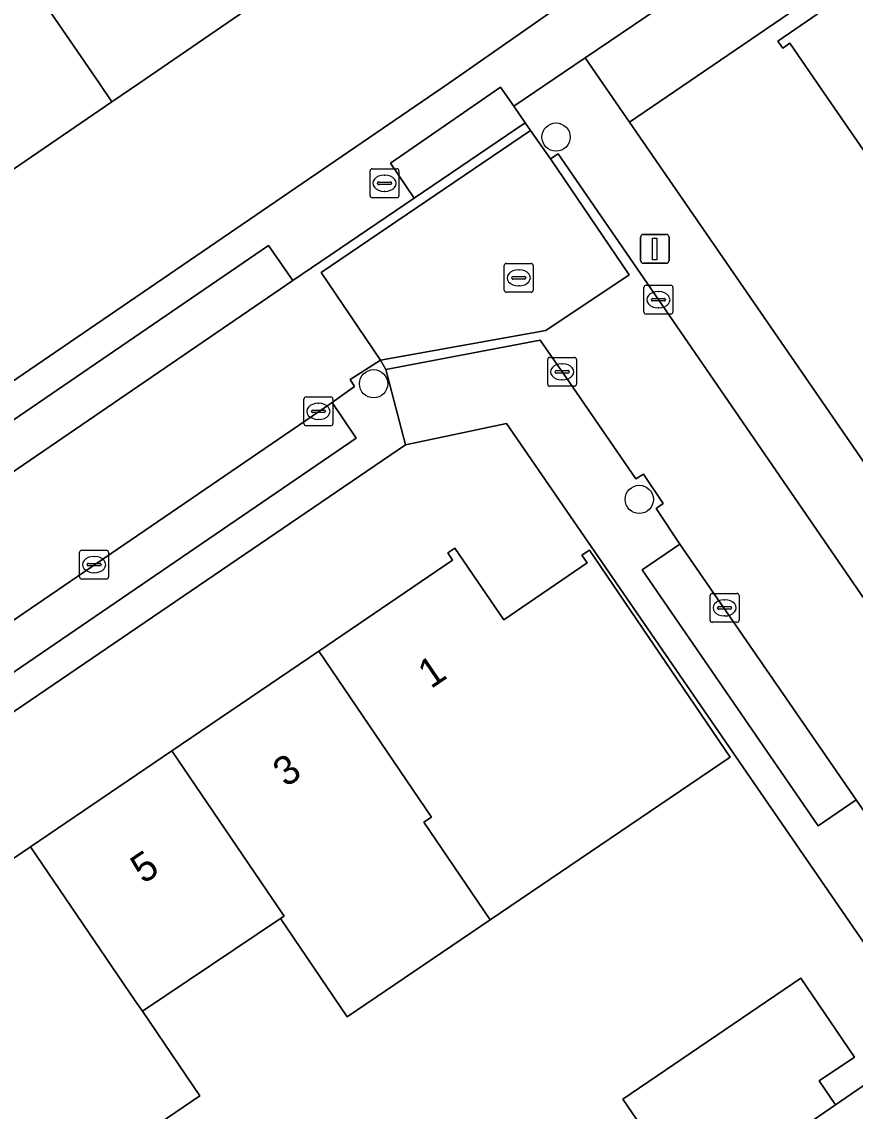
# Model space of a CAD drawing. Extents: x 157445 to 158888, y 383061 to 384688.
# Drawn here: x 158148.42 to 158177.28, y 383464.42 to 383502.14 of the extents above; entities that cross this region are included whole.
import ezdxf

# ---------------------------------------------------------------- set-up
doc = ezdxf.new("R2010")
doc.units = 0
for name, color, linetype in [('IMGEO_Boom', 7, 'Continuous'), ('IMGEO_Brandkraan', 7, 'Continuous'), ('IMGEO_Erf', 7, 'Continuous'), ('IMGEO_Kolk', 7, 'Continuous'), ('IMGEO_Lichtmast', 7, 'Continuous'), ('IMGEO_Pand', 7, 'Continuous'), ('IMGEO_Pand_nummerreeks', 7, 'Continuous'), ('IMGEO_Parkeervlak_open', 7, 'Continuous'), ('IMGEO_Rijbaan_lokaal_open', 7, 'Continuous'), ('IMGEO_Rioolput', 7, 'Continuous'), ('IMGEO_Voetpad_open', 7, 'Continuous')]:
    doc.layers.add(name, color=color, linetype=linetype)

msp = doc.modelspace()

# ---------------------------------------------------------------- linework, layer by layer
at = {"layer": 'IMGEO_Boom'}
for centre in [(158166.918, 383498.147), (158160.602, 383489.605), (158169.801, 383485.602)]:
    msp.add_circle(centre, 0.489, dxfattribs=at)
at = {"layer": 'IMGEO_Brandkraan'}
for p, q in [((158160.48, 383496.122), (158160.48, 383496.974)), ((158160.555, 383497.048), (158161.407, 383497.048)), ((158160.968, 383496.828), (158160.993, 383496.828)), ((158161.481, 383496.974), (158161.481, 383496.122)), ((158160.739, 383496.542), (158160.739, 383496.554)), ((158161.177, 383496.505), (158160.779, 383496.505)), ((158160.782, 383496.591), (158161.18, 383496.591)), ((158161.223, 383496.554), (158161.223, 383496.542)), ((158161.407, 383496.048), (158160.555, 383496.048)), ((158160.991, 383496.268), (158160.966, 383496.268))]:
    msp.add_line(p, q, dxfattribs=at)
for points in [[(158160.48, 383496.122), (158160.48, 383496.974)], [(158160.555, 383497.048), (158161.407, 383497.048)], [(158161.481, 383496.974), (158161.481, 383496.122)], [(158161.407, 383496.048), (158160.555, 383496.048)]]:
    msp.add_lwpolyline(points, dxfattribs=at)
for centre, radius, start, end in [((158160.557, 383496.972), 0.0765, 91.552, 178.448), ((158160.557, 383496.972), 0.0765, 91.552, 178.448), ((158161.405, 383496.972), 0.0765, 1.552, 88.448), ((158161.405, 383496.972), 0.0765, 1.552, 88.448), ((158160.779, 383496.551), 0.0403, 85.8775, 175.7526), ((158160.776, 383496.541), 0.0366, 178.938, 274.7102), ((158161.18, 383496.548), 0.043, 264.8664, 352.4533), ((158161.184, 383496.553), 0.0386, 1.7309, 96.639), ((158160.557, 383496.124), 0.0765, 181.552, 268.448), ((158160.557, 383496.124), 0.0765, 181.552, 268.448), ((158161.405, 383496.124), 0.0765, 271.552, 358.448), ((158161.405, 383496.124), 0.0765, 271.552, 358.448)]:
    msp.add_arc(centre, radius, start, end, dxfattribs=at)
for centre, major_axis, ratio, start_param, end_param in [((158160.967, 383496.548), (-0.387, 0.002), 0.722429, 4.712389, 7.853982), ((158160.992, 383496.548), (-0.39, 0.002), 0.717154, 1.570796, 4.712389)]:
    msp.add_ellipse(centre, major_axis=major_axis, ratio=ratio, start_param=start_param, end_param=end_param, dxfattribs=at)
at = {"layer": 'IMGEO_Erf'}
for points in [[(158099.535, 383456.505), (158112.557, 383465.403), (158163.191, 383500), (158166.785, 383502.503), (158174.8, 383507.947), (158171.578, 383512.706), (158171.33, 383512.536), (158171.16, 383512.783), (158166.413, 383509.536), (158161.426, 383506.125), (158156.37, 383502.667), (158152.47, 383500), (158151.545, 383499.368), (158146.628, 383496.004), (158141.637, 383492.59), (158136.791, 383489.276), (158131.721, 383485.809), (158126.874, 383482.494), (158121.76, 383478.996), (158116.93, 383475.693), (158111.816, 383472.194), (158107.026, 383468.918), (158101.876, 383465.396), (158097.013, 383462.07)], [(158186.515, 383510.296), (158169.458, 383498.667), (158173.045, 383493.459), (158193.833, 383463.284)], [(158178.381, 383496.502), (158175.975, 383500), (158175.016, 383501.394), (158174.769, 383501.224), (158174.599, 383501.472), (158180.671, 383505.651)], [(158170.025, 383463.669), (158169.233, 383464.836), (158175.397, 383469.02), (158177.25, 383466.289), (158176.027, 383465.464), (158176.593, 383464.64), (158179.881, 383466.9), (158165.205, 383488.229), (158161.709, 383487.492), (158141.032, 383473.406)], [(158143.63, 383470.113), (158148.729, 383473.576), (158153.616, 383476.896), (158158.702, 383480.35), (158163.339, 383483.5), (158163.171, 383483.749), (158163.42, 383483.918), (158165.106, 383481.436), (158168.002, 383483.402), (158167.816, 383483.675), (158168.073, 383483.849), (158172.942, 383476.675), (158164.643, 383471.043), (158159.691, 383467.682), (158157.378, 383471.09), (158152.597, 383467.878), (158154.587, 383464.947), (158149.242, 383461.318)]]:
    msp.add_lwpolyline(points, dxfattribs=at)
at = {"layer": 'IMGEO_Kolk'}
for p, q in [((158170.038, 383493.016), (158170.89, 383493.016)), ((158169.963, 383492.09), (158169.963, 383492.942)), ((158170.451, 383492.796), (158170.476, 383492.796)), ((158170.964, 383492.942), (158170.964, 383492.09)), ((158170.222, 383492.51), (158170.222, 383492.522)), ((158170.66, 383492.473), (158170.262, 383492.473)), ((158170.265, 383492.559), (158170.663, 383492.559)), ((158170.474, 383492.236), (158170.449, 383492.236)), ((158170.706, 383492.522), (158170.706, 383492.51)), ((158170.89, 383492.016), (158170.038, 383492.016)), ((158166.629, 383489.593), (158166.629, 383490.445)), ((158166.704, 383490.519), (158167.556, 383490.519)), ((158167.63, 383490.445), (158167.63, 383489.593)), ((158166.888, 383490.013), (158166.888, 383490.025)), ((158167.326, 383489.976), (158166.928, 383489.976)), ((158166.931, 383490.062), (158167.329, 383490.062)), ((158167.117, 383490.299), (158167.142, 383490.299)), ((158167.372, 383490.025), (158167.372, 383490.013)), ((158167.14, 383489.739), (158167.115, 383489.739)), ((158167.556, 383489.519), (158166.704, 383489.519)), ((158158.192, 383488.224), (158158.192, 383489.076)), ((158158.267, 383489.15), (158159.119, 383489.15)), ((158158.68, 383488.93), (158158.705, 383488.93)), ((158159.193, 383489.076), (158159.193, 383488.224)), ((158158.451, 383488.644), (158158.451, 383488.656)), ((158158.889, 383488.607), (158158.491, 383488.607)), ((158158.494, 383488.693), (158158.892, 383488.693)), ((158158.935, 383488.656), (158158.935, 383488.644)), ((158159.119, 383488.15), (158158.267, 383488.15)), ((158158.703, 383488.37), (158158.678, 383488.37)), ((158150.426, 383482.917), (158150.426, 383483.769)), ((158150.501, 383483.843), (158151.353, 383483.843)), ((158150.914, 383483.623), (158150.939, 383483.623)), ((158151.427, 383483.769), (158151.427, 383482.917)), ((158150.685, 383483.337), (158150.685, 383483.349)), ((158151.123, 383483.3), (158150.725, 383483.3)), ((158150.728, 383483.386), (158151.126, 383483.386)), ((158151.169, 383483.349), (158151.169, 383483.337)), ((158151.353, 383482.843), (158150.501, 383482.843)), ((158150.937, 383483.063), (158150.912, 383483.063)), ((158172.253, 383481.419), (158172.253, 383482.271)), ((158172.328, 383482.345), (158173.18, 383482.345)), ((158172.741, 383482.125), (158172.766, 383482.125)), ((158173.254, 383482.271), (158173.254, 383481.419)), ((158172.512, 383481.839), (158172.512, 383481.851)), ((158172.95, 383481.802), (158172.552, 383481.802)), ((158172.555, 383481.888), (158172.953, 383481.888)), ((158172.996, 383481.851), (158172.996, 383481.839)), ((158173.18, 383481.345), (158172.328, 383481.345)), ((158172.764, 383481.565), (158172.739, 383481.565))]:
    msp.add_line(p, q, dxfattribs=at)
for points in [[(158170.038, 383493.016), (158170.89, 383493.016)], [(158169.963, 383492.09), (158169.963, 383492.942)], [(158170.964, 383492.942), (158170.964, 383492.09)], [(158170.89, 383492.016), (158170.038, 383492.016)], [(158166.629, 383489.593), (158166.629, 383490.445)], [(158166.704, 383490.519), (158167.556, 383490.519)], [(158167.63, 383490.445), (158167.63, 383489.593)], [(158167.556, 383489.519), (158166.704, 383489.519)], [(158158.192, 383488.224), (158158.192, 383489.076)], [(158158.267, 383489.15), (158159.119, 383489.15)], [(158159.193, 383489.076), (158159.193, 383488.224)], [(158159.119, 383488.15), (158158.267, 383488.15)], [(158150.426, 383482.917), (158150.426, 383483.769)], [(158150.501, 383483.843), (158151.353, 383483.843)], [(158151.427, 383483.769), (158151.427, 383482.917)], [(158151.353, 383482.843), (158150.501, 383482.843)], [(158172.253, 383481.419), (158172.253, 383482.271)], [(158172.328, 383482.345), (158173.18, 383482.345)], [(158173.254, 383482.271), (158173.254, 383481.419)], [(158173.18, 383481.345), (158172.328, 383481.345)]]:
    msp.add_lwpolyline(points, dxfattribs=at)
for centre, radius, start, end in [((158170.04, 383492.94), 0.0765, 91.552, 178.448), ((158170.04, 383492.94), 0.0765, 91.552, 178.448), ((158170.888, 383492.94), 0.0765, 1.552, 88.448), ((158170.888, 383492.94), 0.0765, 1.552, 88.448), ((158170.262, 383492.519), 0.0403, 85.8775, 175.7526), ((158170.259, 383492.509), 0.0366, 178.938, 274.7102), ((158170.663, 383492.516), 0.043, 264.8664, 352.4533), ((158170.667, 383492.521), 0.0386, 1.7309, 96.639), ((158170.04, 383492.092), 0.0765, 181.552, 268.448), ((158170.04, 383492.092), 0.0765, 181.552, 268.448), ((158170.888, 383492.092), 0.0765, 271.552, 358.448), ((158170.888, 383492.092), 0.0765, 271.552, 358.448), ((158166.706, 383490.443), 0.0765, 91.552, 178.448), ((158166.706, 383490.443), 0.0765, 91.552, 178.448), ((158167.554, 383490.443), 0.0765, 1.552, 88.448), ((158167.554, 383490.443), 0.0765, 1.552, 88.448), ((158166.928, 383490.022), 0.0403, 85.8775, 175.7526), ((158166.925, 383490.012), 0.0366, 178.938, 274.7102), ((158167.329, 383490.019), 0.043, 264.8664, 352.4533), ((158167.333, 383490.024), 0.0386, 1.7309, 96.639), ((158166.706, 383489.595), 0.0765, 181.552, 268.448), ((158166.706, 383489.595), 0.0765, 181.552, 268.448), ((158167.554, 383489.595), 0.0765, 271.552, 358.448), ((158167.554, 383489.595), 0.0765, 271.552, 358.448), ((158158.269, 383489.074), 0.0765, 91.552, 178.448), ((158158.269, 383489.074), 0.0765, 91.552, 178.448), ((158159.117, 383489.074), 0.0765, 1.552, 88.448), ((158159.117, 383489.074), 0.0765, 1.552, 88.448), ((158158.491, 383488.653), 0.0403, 85.8775, 175.7526), ((158158.488, 383488.643), 0.0366, 178.938, 274.7102), ((158158.892, 383488.65), 0.043, 264.8664, 352.4533), ((158158.896, 383488.655), 0.0386, 1.7309, 96.639), ((158158.269, 383488.226), 0.0765, 181.552, 268.448), ((158158.269, 383488.226), 0.0765, 181.552, 268.448), ((158159.117, 383488.226), 0.0765, 271.552, 358.448), ((158159.117, 383488.226), 0.0765, 271.552, 358.448), ((158150.503, 383483.767), 0.0765, 91.552, 178.448), ((158150.503, 383483.767), 0.0765, 91.552, 178.448), ((158151.351, 383483.767), 0.0765, 1.552, 88.448), ((158151.351, 383483.767), 0.0765, 1.552, 88.448), ((158150.725, 383483.346), 0.0403, 85.8775, 175.7526), ((158150.722, 383483.336), 0.0366, 178.938, 274.7102), ((158151.126, 383483.343), 0.043, 264.8664, 352.4533), ((158151.13, 383483.348), 0.0386, 1.7309, 96.639), ((158150.503, 383482.919), 0.0765, 181.552, 268.448), ((158150.503, 383482.919), 0.0765, 181.552, 268.448), ((158151.351, 383482.919), 0.0765, 271.552, 358.448), ((158151.351, 383482.919), 0.0765, 271.552, 358.448), ((158172.33, 383482.269), 0.0765, 91.552, 178.448), ((158172.33, 383482.269), 0.0765, 91.552, 178.448), ((158173.178, 383482.269), 0.0765, 1.552, 88.448), ((158173.178, 383482.269), 0.0765, 1.552, 88.448), ((158172.552, 383481.848), 0.0403, 85.8775, 175.7526), ((158172.549, 383481.838), 0.0366, 178.938, 274.7102), ((158172.953, 383481.845), 0.043, 264.8664, 352.4533), ((158172.957, 383481.85), 0.0386, 1.7309, 96.639), ((158172.33, 383481.421), 0.0765, 181.552, 268.448), ((158172.33, 383481.421), 0.0765, 181.552, 268.448), ((158173.178, 383481.421), 0.0765, 271.552, 358.448), ((158173.178, 383481.421), 0.0765, 271.552, 358.448)]:
    msp.add_arc(centre, radius, start, end, dxfattribs=at)
for centre, major_axis, ratio, start_param, end_param in [((158170.45, 383492.516), (-0.387, 0.002), 0.722429, 4.712389, 7.853982), ((158170.475, 383492.516), (-0.39, 0.002), 0.717154, 1.570796, 4.712389), ((158167.116, 383490.019), (-0.387, 0.002), 0.722429, 4.712389, 7.853982), ((158167.141, 383490.019), (-0.39, 0.002), 0.717154, 1.570796, 4.712389), ((158158.679, 383488.65), (-0.387, 0.002), 0.722429, 4.712389, 7.853982), ((158158.704, 383488.65), (-0.39, 0.002), 0.717154, 1.570796, 4.712389), ((158150.913, 383483.343), (-0.387, 0.002), 0.722429, 4.712389, 7.853982), ((158150.938, 383483.343), (-0.39, 0.002), 0.717154, 1.570796, 4.712389), ((158172.74, 383481.845), (-0.387, 0.002), 0.722429, 4.712389, 7.853982), ((158172.765, 383481.845), (-0.39, 0.002), 0.717154, 1.570796, 4.712389)]:
    msp.add_ellipse(centre, major_axis=major_axis, ratio=ratio, start_param=start_param, end_param=end_param, dxfattribs=at)
at = {"layer": 'IMGEO_Lichtmast'}
for p, q in [((158169.843, 383493.877), (158169.843, 383494.677)), ((158169.843, 383494.677), (158169.843, 383493.877)), ((158169.943, 383494.777), (158170.733, 383494.777)), ((158170.733, 383494.777), (158169.943, 383494.777)), ((158170.833, 383494.677), (158170.833, 383493.877)), ((158170.833, 383493.877), (158170.833, 383494.677)), ((158170.733, 383493.777), (158169.943, 383493.777)), ((158169.943, 383493.777), (158170.733, 383493.777))]:
    msp.add_line(p, q, dxfattribs=at)
msp.add_lwpolyline([(158170.263, 383494.652), (158170.413, 383494.652), (158170.413, 383493.902), (158170.263, 383493.902), (158170.263, 383494.652)], dxfattribs=at)
for centre, start, end in [((158169.943, 383494.677), 90, 180), ((158169.943, 383494.677), 90, 180), ((158170.733, 383494.677), 0, 90), ((158170.733, 383494.677), 360, 90), ((158169.943, 383493.877), 180, 270), ((158169.943, 383493.877), 180, 270), ((158170.733, 383493.877), 270, 0), ((158170.733, 383493.877), 270, 0)]:
    msp.add_arc(centre, 0.1, start, end, dxfattribs=at)
at = {"layer": 'IMGEO_Pand'}
for points in [[(158156.37, 383502.667), (158152.593, 383508.188), (158147.769, 383504.889), (158151.113, 383500), (158151.545, 383499.368), (158152.47, 383500)], [(158178.381, 383496.502), (158183.52, 383500), (158184.227, 383500.482), (158187.003, 383502.372), (158183.436, 383507.554), (158180.671, 383505.651), (158174.599, 383501.472), (158174.769, 383501.224), (158175.016, 383501.394), (158175.975, 383500)], [(158147.769, 383504.889), (158142.851, 383501.526), (158143.895, 383500), (158146.628, 383496.004), (158151.545, 383499.368), (158151.113, 383500)], [(158162.346, 383474.427), (158164.643, 383471.043), (158172.942, 383476.675), (158168.073, 383483.849), (158167.816, 383483.675), (158168.002, 383483.402), (158165.106, 383481.436), (158163.42, 383483.918), (158163.171, 383483.749), (158163.339, 383483.5), (158158.702, 383480.35), (158162.605, 383474.601)], [(158158.702, 383480.35), (158153.616, 383476.896), (158157.502, 383471.173), (158157.378, 383471.09), (158159.691, 383467.682), (158164.643, 383471.043), (158162.346, 383474.427), (158162.605, 383474.601)], [(158153.616, 383476.896), (158148.729, 383473.576), (158152.349, 383468.243), (158152.597, 383467.878), (158157.378, 383471.09), (158157.502, 383471.173)], [(158152.597, 383467.878), (158152.349, 383468.243), (158148.729, 383473.576), (158143.63, 383470.113), (158143.462, 383470.362), (158143.214, 383470.194), (158146.023, 383466.058), (158147.403, 383464.026), (158149.242, 383461.318), (158154.587, 383464.947)], [(158176.593, 383464.64), (158176.027, 383465.464), (158177.25, 383466.289), (158175.397, 383469.02), (158169.233, 383464.836), (158170.025, 383463.669), (158171.665, 383461.253), (158174.121, 383462.941)]]:
    msp.add_lwpolyline(points, close=True, dxfattribs=at)
at = {"layer": 'IMGEO_Parkeervlak_open'}
for points in [[(158165.846, 383498.64), (158165.452, 383499.214), (158165, 383499.874), (158161.183, 383497.244), (158162.003, 383496.034)], [(158143.844, 383483.632), (158157.809, 383493.177), (158156.961, 383494.391), (158143.007, 383484.844)], [(158141.051, 383476.583), (158140.847, 383476.444), (158141.696, 383475.217), (158160.003, 383487.724), (158159.166, 383488.956)], [(158171.207, 383484.055), (158169.899, 383483.16), (158175.997, 383474.299), (158177.306, 383475.194)]]:
    msp.add_lwpolyline(points, close=True, dxfattribs=at)
at = {"layer": 'IMGEO_Rijbaan_lokaal_open'}
for points in [[(158138.68, 383480.098), (158141.051, 383476.583), (158159.166, 383488.956), (158159.947, 383489.505), (158159.788, 383489.754), (158160.847, 383490.423), (158158.784, 383493.462), (158166.033, 383498.375), (158165.846, 383498.64), (158162.003, 383496.034), (158157.809, 383493.177), (158143.844, 383483.632), (158141.057, 383481.727)], [(158160.847, 383490.423), (158166.565, 383491.448), (158169.456, 383493.38), (158166.723, 383497.396), (158166.033, 383498.375), (158158.784, 383493.462)]]:
    msp.add_lwpolyline(points, close=True, dxfattribs=at)
msp.add_lwpolyline([(158190.451, 383463.423), (158178.493, 383480.827), (158170.83, 383491.981), (158166.995, 383497.562), (158166.723, 383497.396), (158169.456, 383493.38), (158166.565, 383491.448), (158160.847, 383490.423), (158161.029, 383490.096), (158166.372, 383491.119), (158167.368, 383489.672), (158169.682, 383486.308), (158169.949, 383486.472), (158170.628, 383485.464), (158170.383, 383485.281), (158171.207, 383484.055), (158177.306, 383475.194), (158182.738, 383467.36), (158182.971, 383467.513), (158183.672, 383466.527), (158183.423, 383466.337), (158183.916, 383465.644), (158190.158, 383456.577)], dxfattribs=at)
at = {"layer": 'IMGEO_Rioolput'}
for p, q in [((158165.202, 383493.774), (158166.054, 383493.774)), ((158165.127, 383492.848), (158165.127, 383493.7)), ((158165.615, 383493.554), (158165.64, 383493.554)), ((158166.128, 383493.7), (158166.128, 383492.848)), ((158165.386, 383493.268), (158165.386, 383493.28)), ((158165.824, 383493.231), (158165.426, 383493.231)), ((158165.429, 383493.317), (158165.827, 383493.317)), ((158165.638, 383492.994), (158165.613, 383492.994)), ((158165.87, 383493.28), (158165.87, 383493.268)), ((158166.054, 383492.774), (158165.202, 383492.774))]:
    msp.add_line(p, q, dxfattribs=at)
for points in [[(158165.202, 383493.774), (158166.054, 383493.774)], [(158165.127, 383492.848), (158165.127, 383493.7)], [(158166.128, 383493.7), (158166.128, 383492.848)], [(158166.054, 383492.774), (158165.202, 383492.774)]]:
    msp.add_lwpolyline(points, dxfattribs=at)
for centre, radius, start, end in [((158165.204, 383493.698), 0.0765, 91.552, 178.448), ((158165.204, 383493.698), 0.0765, 91.552, 178.448), ((158166.052, 383493.698), 0.0765, 1.552, 88.448), ((158166.052, 383493.698), 0.0765, 1.552, 88.448), ((158165.426, 383493.277), 0.0403, 85.8775, 175.7526), ((158165.423, 383493.267), 0.0366, 178.938, 274.7102), ((158165.827, 383493.274), 0.043, 264.8664, 352.4533), ((158165.831, 383493.279), 0.0386, 1.7309, 96.639), ((158165.204, 383492.85), 0.0765, 181.552, 268.448), ((158165.204, 383492.85), 0.0765, 181.552, 268.448), ((158166.052, 383492.85), 0.0765, 271.552, 358.448), ((158166.052, 383492.85), 0.0765, 271.552, 358.448)]:
    msp.add_arc(centre, radius, start, end, dxfattribs=at)
for centre, major_axis, ratio, start_param, end_param in [((158165.614, 383493.274), (-0.387, 0.002), 0.722429, 4.712389, 7.853982), ((158165.639, 383493.274), (-0.39, 0.002), 0.717154, 1.570796, 4.712389)]:
    msp.add_ellipse(centre, major_axis=major_axis, ratio=ratio, start_param=start_param, end_param=end_param, dxfattribs=at)
at = {"layer": 'IMGEO_Voetpad_open'}
for points in [[(158186.515, 383510.296), (158185.214, 383512.203), (158189.847, 383515.373), (158189.663, 383515.631), (158177.273, 383507.024), (158177.152, 383507.139), (158167.926, 383500.89), (158168.539, 383500), (158169.458, 383498.667)], [(158156.961, 383494.391), (158157.809, 383493.177), (158162.003, 383496.034), (158161.183, 383497.244), (158165, 383499.874), (158165.452, 383499.214), (158167.926, 383500.89), (158177.152, 383507.139), (158176.033, 383508.796), (158174.8, 383507.947), (158166.785, 383502.503), (158163.191, 383500), (158112.557, 383465.403), (158114.04, 383463.232), (158123.804, 383469.901), (158122.967, 383471.113), (158140.215, 383482.934), (158141.057, 383481.727), (158143.844, 383483.632), (158143.007, 383484.844)]]:
    msp.add_lwpolyline(points, close=True, dxfattribs=at)
for points in [[(158193.833, 383463.284), (158173.045, 383493.459), (158169.458, 383498.667), (158168.539, 383500), (158167.926, 383500.89), (158165.452, 383499.214), (158165.846, 383498.64), (158166.033, 383498.375), (158166.723, 383497.396), (158166.995, 383497.562), (158170.83, 383491.981), (158178.493, 383480.827), (158179.784, 383481.727), (158191.749, 383464.34)], [(158202.722, 383435.538), (158182.597, 383464.745), (158183.916, 383465.644), (158183.423, 383466.337), (158183.672, 383466.527), (158182.971, 383467.513), (158182.738, 383467.36), (158177.306, 383475.194), (158175.997, 383474.299), (158169.899, 383483.16), (158171.207, 383484.055), (158170.383, 383485.281), (158170.628, 383485.464), (158169.949, 383486.472), (158169.682, 383486.308), (158167.368, 383489.672), (158166.372, 383491.119), (158161.029, 383490.096), (158161.709, 383487.492), (158165.205, 383488.229), (158179.881, 383466.9), (158180.828, 383465.523), (158202.62, 383433.853)], [(158141.032, 383473.406), (158161.709, 383487.492), (158161.029, 383490.096), (158160.847, 383490.423), (158159.788, 383489.754), (158159.947, 383489.505), (158159.166, 383488.956), (158160.003, 383487.724), (158141.696, 383475.217)], [(158177.876, 383463.466), (158180.828, 383465.523), (158179.881, 383466.9), (158176.593, 383464.64), (158174.121, 383462.941)]]:
    msp.add_lwpolyline(points, dxfattribs=at)

# ---------------------------------------------------------------- texts
at = {"layer": 'IMGEO_Pand_nummerreeks'}
for s, rotation, p in [('1', 34.1856, (158162.585, 383479.023)), ('3', 34.1884, (158157.564, 383475.612)), ('5', 34.1884, (158152.636, 383472.265))]:
    msp.add_text(s, height=1, rotation=rotation, dxfattribs=at).set_placement(p)

doc.saveas('drawing.dxf')
